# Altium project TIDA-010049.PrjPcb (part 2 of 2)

## Sheet TIDA-010049_DigitalInputChan.SchDoc
size 431 x 279 mm; Date: Not shown in title block; ApprovedBy: Not shown in title block; CheckedBy: Not shown in title block; Author: Not shown in title block; CompanyName: Not shown in title block; Engineer: Not shown in title block; Organization: Not shown in title block; Address1: Not shown in title block; Address2: Not shown in title block; Address3: Not shown in title block; Address4: Not shown in title block; DocumentNumber: 2; Revision: Use project parameter SCH_Rev; SheetNumber: 2; SheetTotal: 3; PageSetup: Record=PageOptions¦CenterHorizontal=True¦CenterVertical=True¦PrintScale=1.00¦XCorrection=1.00¦YCorrection=1.00¦PrintKind=0¦BorderSize=5000000¦LeftOffset=0¦BottomOffset=0¦Orientation=2¦PaperLength=1000¦PaperWidth=1000¦Scale=100¦PaperSource=15¦PrintQuality=600¦MediaType=1¦DitherType=10¦PaperKind=Letter¦PrintScaleMode=1
Used 8 times, as channels DI1, DI2, DI3, DI4, DI5, DI6, DI7, DI8. Parts and nets are listed once, with the designators drawn on the sheet.
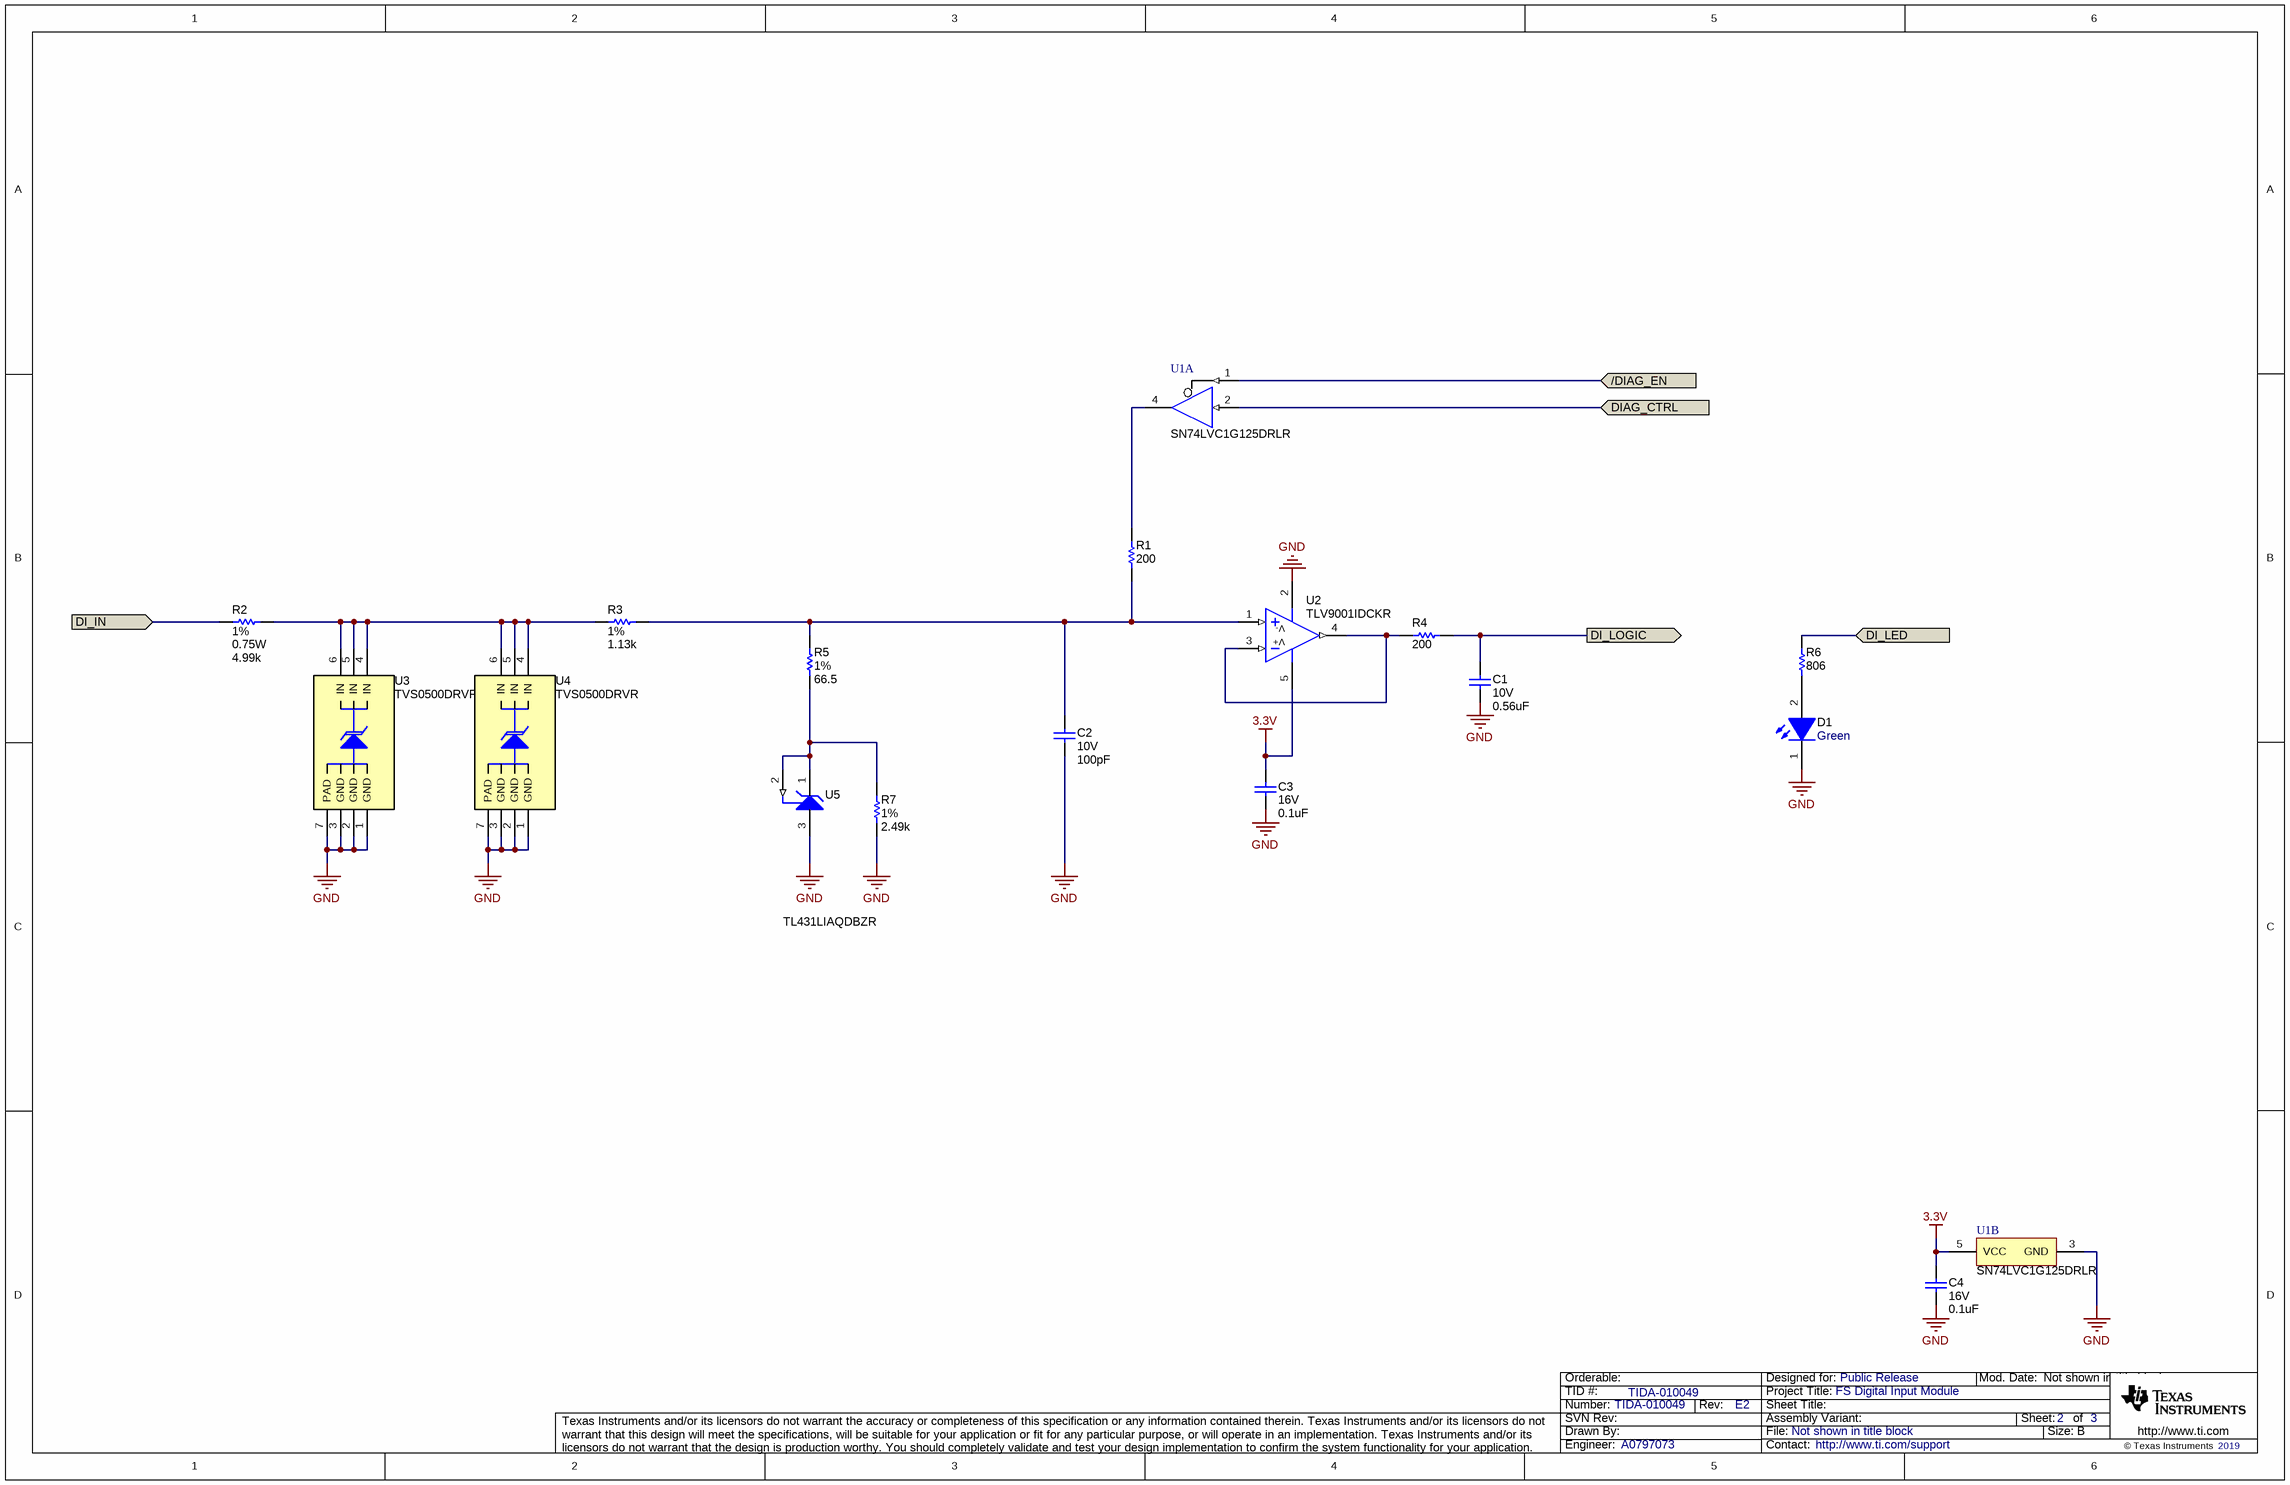
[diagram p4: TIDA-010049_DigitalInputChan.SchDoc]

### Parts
C1  VDC_V: 10V  ValueDisplayed: 0.56uF  [0603]  (hidden comment: GRM188R71A564KA61D)
C2  VDC_V: 10V  ValueDisplayed: 100pF  [0603]  (hidden comment: 0603ZC101KAT2A)
C3  VDC_V: 16V  ValueDisplayed: 0.1uF  [0603]  (hidden comment: GRM188R71C104KA01D)
C4  VDC_V: 16V  ValueDisplayed: 0.1uF  [0603]  (hidden comment: GRM188R71C104KA01D)
D1  value Green  [WL-SMCW_GREEN]  (hidden comment: 150060GS75000)
R1  ValueDisplayed: 200  [0603]  (hidden comment: CRCW0603200RJNEA)
R2  Tolerance_%: 1%  Value2: 0.75W  ValueDisplayed: 4.99k  [2010]  (hidden comment: CRCW20104K99FKEF)
R3  Tolerance_%: 1%  ValueDisplayed: 1.13k  [0603]  (hidden comment: RC0603FR-071K13L)
R4  ValueDisplayed: 200  [0603]  (hidden comment: CRCW0603200RJNEA)
R5  Tolerance_%: 1%  ValueDisplayed: 66.5  [0603]  (hidden comment: RC0603FR-0766R5L)
R6  ValueDisplayed: 806  [0603]  (hidden comment: RC0603FR-07806RL)
R7  Tolerance_%: 1%  ValueDisplayed: 2.49k  [0603]  (hidden comment: RC0603FR-072K49L)
U1  SN74LVC1G125DRLR  [DRL0005A]  (parts A,B of 2)
U2  TLV9001IDCKR  [DCK0005A_N]
U3  TVS0500DRVR  [DRV0006A]
U4  TVS0500DRVR  [DRV0006A]
U5  TL431LIAQDBZR  [DBZ0003A_N]

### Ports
/DIAG_EN (in), DI_IN (in), DI_LED (in), DI_LOGIC (out), DIAG_CTRL (in)

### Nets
3.3V: C3.1 C4.1 U1.5(VCC) U2.5(V+)
GND: C1.2 C2.2 C3.2 C4.2 D1.1(K) R7.1 U1.3(GND) U2.2(V-) U3.1(GND) U3.2(GND) U3.3(GND) U3.7(PAD) U4.1(GND) U4.2(GND) U4.3(GND) U4.7(PAD) U5.3(ANODE)
/DIAG_EN: U1.1(~{OE}) ; port /DIAG_EN
DI_IN: R2.2 ; port DI_IN
DI_LED: R6.2 ; port DI_LED
DI_LOGIC: C1.1 R4.2 ; port DI_LOGIC
DIAG_CTRL: U1.2(A) ; port DIAG_CTRL
NetC2_1: C2.1 R1.1 R3.1 R5.2 U2.1(IN+)
NetD1_2: D1.2(A) R6.1
NetR1_2: R1.2 U1.4(Y)
NetR2_1: R2.1 R3.2 U3.4(IN) U3.5(IN) U3.6(IN) U4.4(IN) U4.5(IN) U4.6(IN)
NetR4_1: R4.1 U2.3(IN-) U2.4(OUT)
NetR5_1: R5.1 R7.2 U5.1(CATHODE) U5.2(REF)

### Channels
DI1: designators end in _1; ports /DIAG_EN=/DIAG_EN1 DI_IN=DI_IN1 DI_LED=DI_LED1 DI_LOGIC=DI_LOGIC1 DIAG_CTRL=DIAG_CTRL1
DI2: designators end in _2; ports /DIAG_EN=/DIAG_EN2 DI_IN=DI_IN2 DI_LED=DI_LED2 DI_LOGIC=DI_LOGIC2 DIAG_CTRL=DIAG_CTRL2
DI3: designators end in _3; ports /DIAG_EN=/DIAG_EN3 DI_IN=DI_IN3 DI_LED=DI_LED3 DI_LOGIC=DI_LOGIC3 DIAG_CTRL=DIAG_CTRL3
DI4: designators end in _4; ports /DIAG_EN=/DIAG_EN4 DI_IN=DI_IN4 DI_LED=DI_LED4 DI_LOGIC=DI_LOGIC4 DIAG_CTRL=DIAG_CTRL4
DI5: designators end in _5; ports /DIAG_EN=/DIAG_EN5 DI_IN=DI_IN5 DI_LED=DI_LED5 DI_LOGIC=DI_LOGIC5 DIAG_CTRL=DIAG_CTRL5
DI6: designators end in _6; ports /DIAG_EN=/DIAG_EN6 DI_IN=DI_IN6 DI_LED=DI_LED6 DI_LOGIC=DI_LOGIC6 DIAG_CTRL=DIAG_CTRL6
DI7: designators end in _7; ports /DIAG_EN=/DIAG_EN7 DI_IN=DI_IN7 DI_LED=DI_LED7 DI_LOGIC=DI_LOGIC7 DIAG_CTRL=DIAG_CTRL7
DI8: designators end in _8; ports /DIAG_EN=/DIAG_EN8 DI_IN=DI_IN8 DI_LED=DI_LED8 DI_LOGIC=DI_LOGIC8 DIAG_CTRL=DIAG_CTRL8

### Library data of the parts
C1 = CMP-0007374-4: CAP, CERM, 0.56 uF, 10 V, +/- 10%, X7R, 0603; Manufacturer: MuRata; TaMin_C: -55°C; Polarized: N; SizeAreaWB_mm2: 4.68; Value1: Unknown; U/M: EA; Value: 0.56uF; TaMax_C: 125°C; SizeZ_mm: 1; SizeX_mm: 1.6; SizeY_mm: 0.8; SizeArea_mm2: 1.28; Cap_F: 560nF; AEC Category: Q200
C2 = CMP-0006812-4: CAP, CERM, 100 pF, 10 V, +/- 10%, X7R, 0603; Manufacturer: AVX; TaMin_C: -55°C; Polarized: N; SizeAreaWB_mm2: 4.68; Value1: Unknown; U/M: EA; Value: 100pF; TaMax_C: 125°C; SizeZ_mm: 1; SizeX_mm: 1.6; SizeY_mm: 0.8; SizeArea_mm2: 1.28; AEC Category: Q200
C3 C4 = CMP-0007378-5: CAP, CERM, 0.1 uF, 16 V, +/- 10%, X7R, 0603; Manufacturer: MuRata; TaMin_C: -55°C; Polarized: N; SizeAreaWB_mm2: 4.68; Value1: Unknown; U/M: EA; Value: 0.1uF; TaMax_C: 125°C; SizeZ_mm: 1; SizeX_mm: 1.6; SizeY_mm: 0.8; SizeArea_mm2: 1.28; Cap_F: 100nF; AEC Category: Q200
D1 = CMP-0002905-2: LED, Green, SMD; Manufacturer: Wurth Elektronik; Value1: W; Type: InGaN; Value2: 3.2V; Io_A: 20mA; Angle: 140; Tjmax_C: 85°C
R1 R4 = CMP-0025752-3: RES, 200, 5%, 0.1 W, 0603; Manufacturer: Vishay-Dale; Power_W: 100mW; TempCo: 200 ppm/C; Value_Code: 200R; U/M: EA; Value: 200; EIA_Code: E24; SizeX_mm: 1.6; SizeY_mm: 0.8; SizeZ_mm: 1; Value2: 0.1W; SizeArea_mm2: 1.28; VDC_V: 75V; AEC Category: Q200
R2 = CMP-0016428-1: RES, 4.99 k, 1%, 0.75 W, AEC-Q200 Grade 0, 2010; Manufacturer: Vishay-Dale; Power_W: 750mW; TempCo: 100 ppm/C; Value_Code: 4k99; U/M: EA; Value: 4.99k; EIA_Code: E96; SizeX_mm: 5; SizeY_mm: 2.5; SizeZ_mm: 1.66; SizeArea_mm2: 12.5; AEC Qualified: Y; VDC_V: 400V; AEC Grade: 0; AEC Category: Q200
R3 = CMP-0022867-5: RES, 1.13 k, 1%, 0.1 W, 0603; Manufacturer: Yageo; Power_W: 100mW; TempCo: 100 ppm/C; Value_Code: 1k13; Value: 1.13k; EIA_Code: E96; SizeX_mm: 1.6; SizeY_mm: 0.8; SizeZ_mm: 1; Value2: 0.1W; SizeArea_mm2: 1.28; AEC Qualified: N; VDC_V: 75V; AEC Category: Q200; SizeAreaWB_mm2: 4.68
R5 = CMP-0023233-5: RES, 66.5, 1%, 0.1 W, 0603; Manufacturer: Yageo; Power_W: 100mW; TempCo: 100 ppm/C; Value_Code: 66R5; Value: 66.5; EIA_Code: E96; SizeX_mm: 1.6; SizeY_mm: 0.8; SizeZ_mm: 1; Value2: 0.1W; SizeArea_mm2: 1.28; AEC Qualified: N; VDC_V: 75V; AEC Category: Q200; SizeAreaWB_mm2: 4.68
R6 = CMP-0023284-5: RES, 806, 1%, 0.1 W, 0603; Manufacturer: Yageo; Power_W: 100mW; TempCo: 100 ppm/C; Value_Code: 806R; Value: 806; EIA_Code: E96; SizeX_mm: 1.6; SizeY_mm: 0.8; SizeZ_mm: 1; Value2: 0.1W; SizeArea_mm2: 1.28; AEC Qualified: N; VDC_V: 75V; AEC Category: Q200; SizeAreaWB_mm2: 4.68
R7 = CMP-0022990-5: RES, 2.49 k, 1%, 0.1 W, 0603; Manufacturer: Yageo; Power_W: 100mW; TempCo: 100 ppm/C; Value_Code: 2k49; Value: 2.49k; EIA_Code: E96; SizeX_mm: 1.6; SizeY_mm: 0.8; SizeZ_mm: 1; Value2: 0.1W; SizeArea_mm2: 1.28; AEC Qualified: N; VDC_V: 75V; AEC Category: Q200; SizeAreaWB_mm2: 4.68
U1 = CMP-0051312-3: Single Bus Buffer Gate With 3-State Outputs, DRL0005A, LARGE T&R; Manufacturer: Texas Instruments; Output Type: CMOS; tpd @ Nom Voltage(Max)(ns): 9,5.5,4.5,4; Schmitt Trigger: No; Input Type: CMOS/TTL; Voltage(Nom)(V): 1.8,2.5,3.3,5; Technology Family: LVC; VCC(Max)(V): 5.5; F @ Nom Voltage(Max)(Mhz): 150; Sub-Family: Non-Inverting Buffer/Driver; Bits(#): 1; ICC @ Nom Voltage(Max)(mA): 0.01; Rating: Catalog; VCC(Min)(V): 1.65; Logic: True; Output Drive (IOL/IOH)(Max)(mA): 32/-32; 3-State Output: Yes; AEC Category: Q200; AEC Qualified: N; CompType: IC; SizeX_mm: 1.6; SizeZ_mm: 0.6
U2 = CMP-0081556-1: Low-Power, Rail-to-Rail In and Out, 1-MHz Operational Amplifier, DCK0005A (SOT-SC70-5); Alternate PartNumber: TLV9001IDCKT; Alternate Manufacturer: Texas Instruments; SizeAreaWB_mm2: 9.3; SizeZ_mm: 1.1; SizeX_mm: 2.1; SizeY_mm: 2; SizeArea_mm2: 4.2; CompType: IC; AEC Qualified: N; AEC Category: Q200
U3 U4 = CMP-0077837-1: 5-V Precision Surge Protection Clamp, DRV0006A (WSON-6); Alternate Manufacturer: Texas Instruments; SizeAreaWB_mm2: 9.0; SizeZ_mm: 0.8; SizeX_mm: 2.0; SizeArea_mm2: 4.0; CompType: IC; AEC Qualified: N; AEC Category: Q200
U5 = CMP-0084728-1: Programmable Shunt Regulator with Optimized Reference Current, DBZ0003A (SOT-23-3); Manufacturer: Texas Instruments; AEC Qualified: N; SizeZ_mm: 1.12; CompType: IC; SizeY_mm: 3; AEC Category: Q200; SizeX_mm: 2.5; SizeAreaWB_mm2: 14; SizeArea_mm2: 7.5

## Sheet TIDA-010049_LED.SchDoc
size 431 x 279 mm; Date: Not shown in title block; ApprovedBy: Not shown in title block; CheckedBy: Not shown in title block; Author: Not shown in title block; CompanyName: Not shown in title block; Engineer: Not shown in title block; Organization: Not shown in title block; Address1: Not shown in title block; Address2: Not shown in title block; Address3: Not shown in title block; Address4: Not shown in title block; DocumentNumber: 2; Revision: Use project parameter SCH_Rev; SheetNumber: 2; SheetTotal: 3; PageSetup: Record=PageOptions¦CenterHorizontal=True¦CenterVertical=True¦PrintScale=1.00¦XCorrection=1.00¦YCorrection=1.00¦PrintKind=0¦BorderSize=5000000¦LeftOffset=0¦BottomOffset=0¦Orientation=2¦PaperLength=1000¦PaperWidth=1000¦Scale=100¦PaperSource=15¦PrintQuality=600¦MediaType=1¦DitherType=10¦PaperKind=Letter¦PrintScaleMode=1
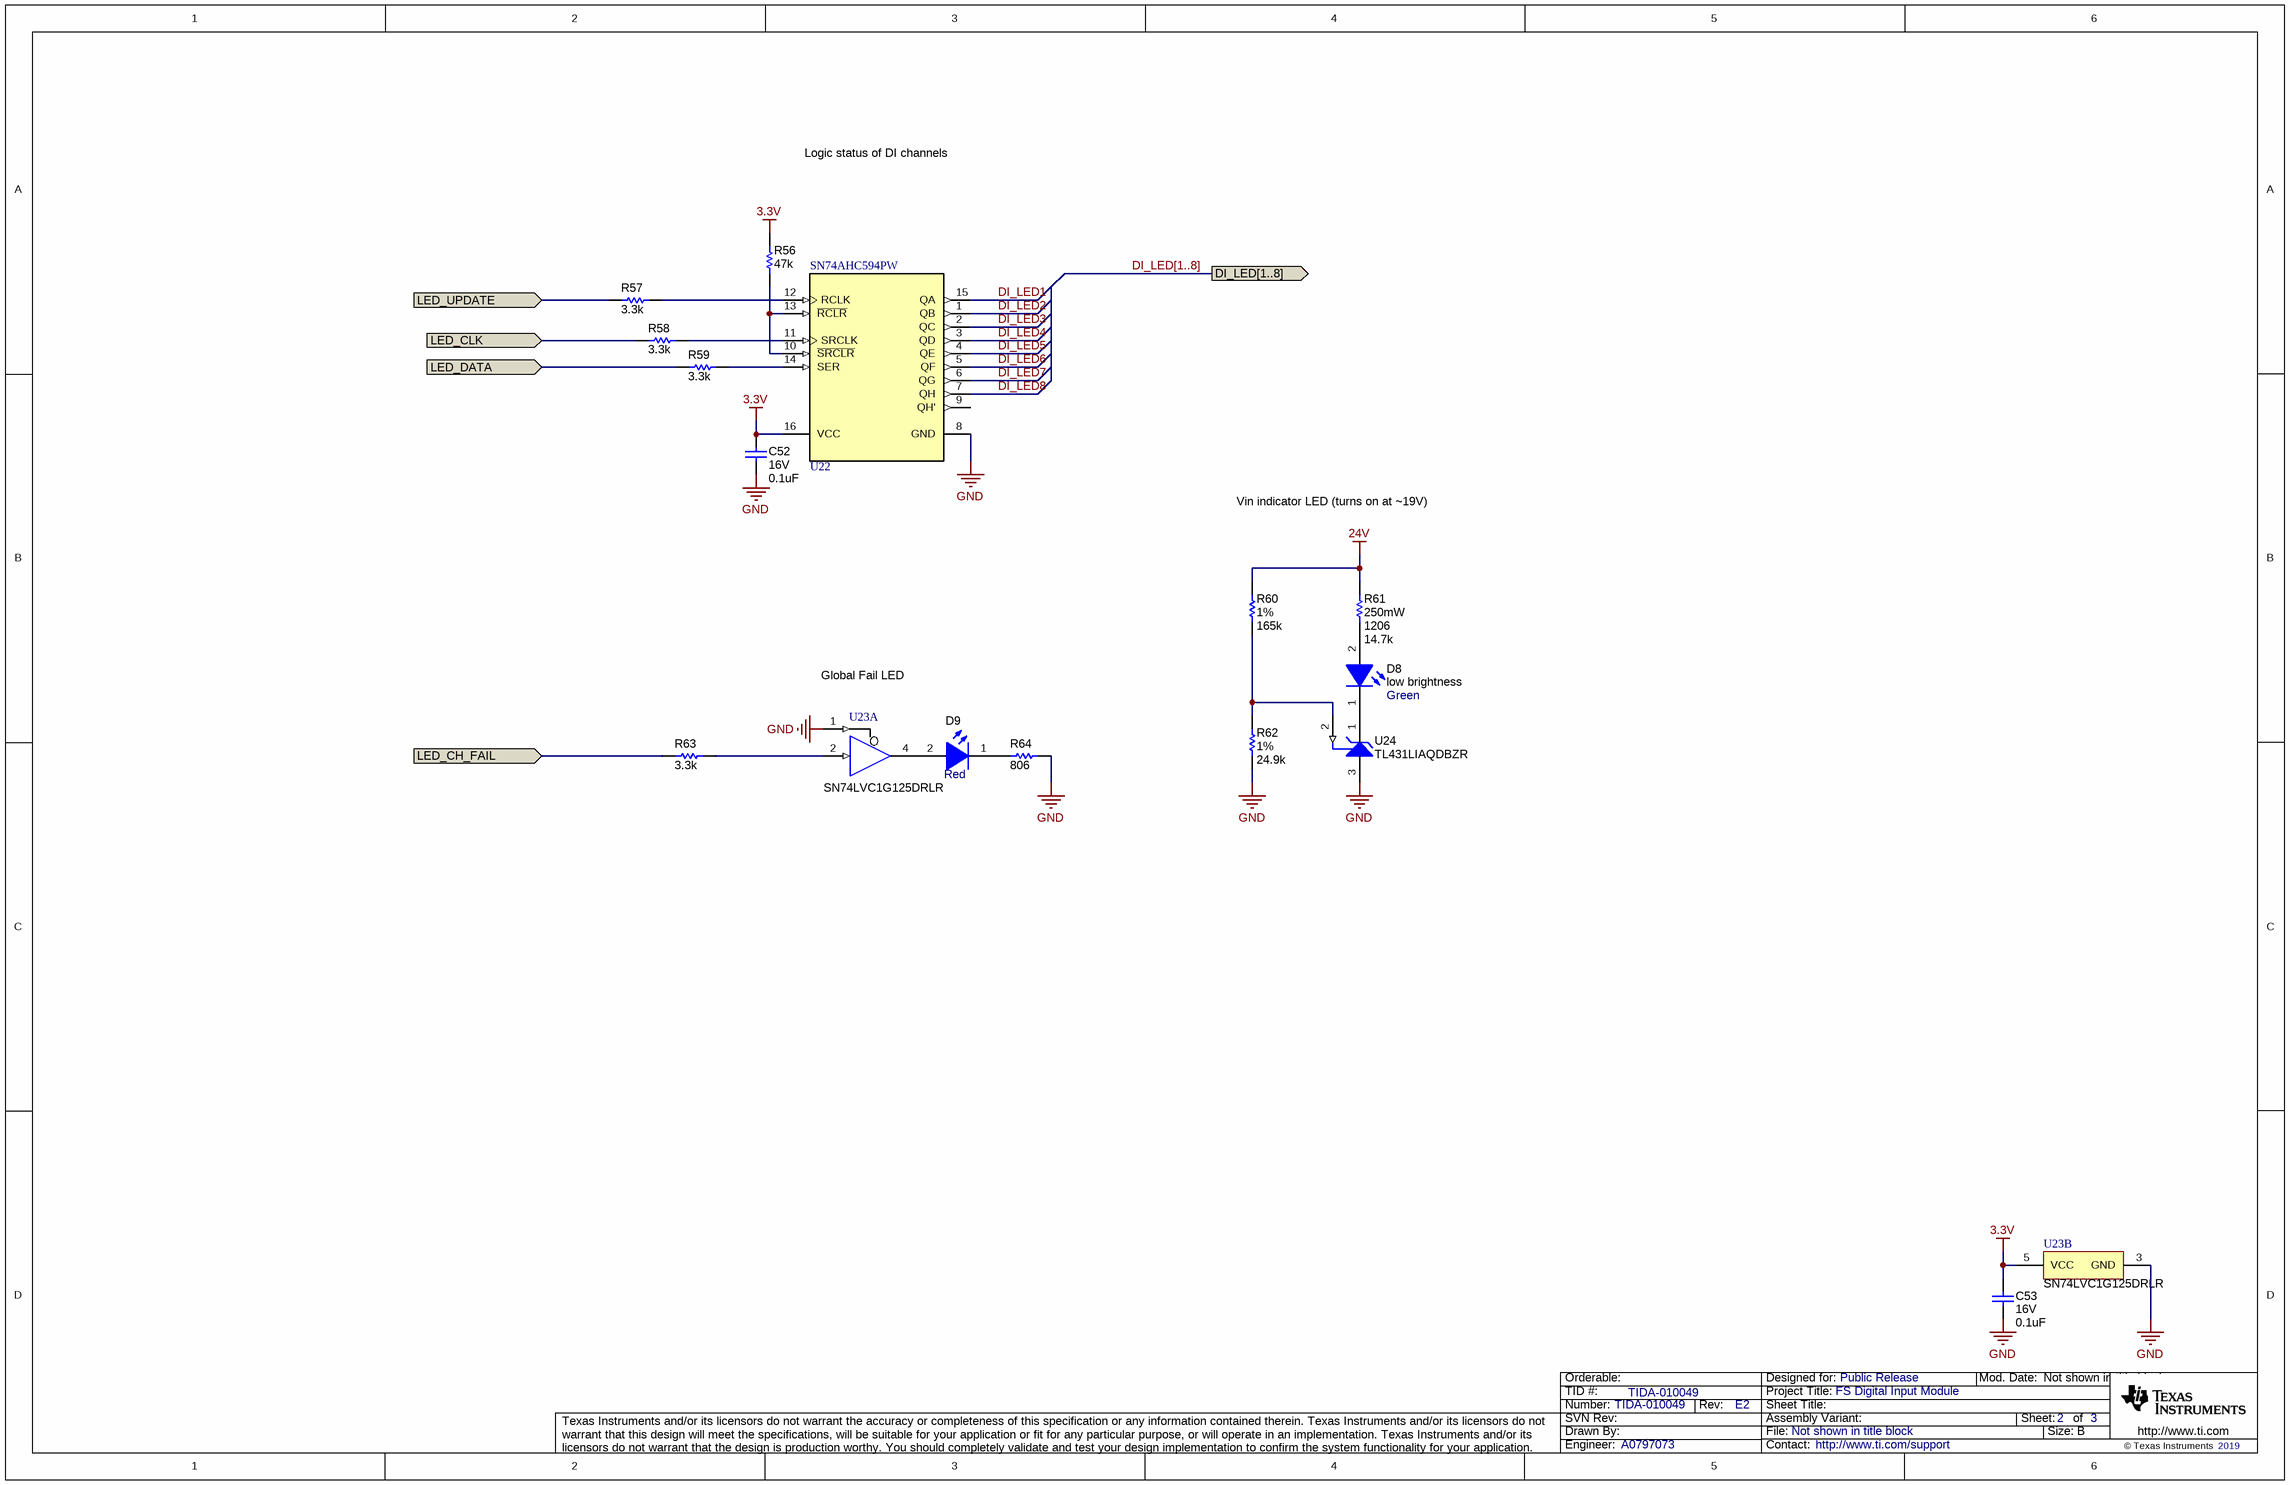
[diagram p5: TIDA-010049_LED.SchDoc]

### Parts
C52  VDC_V: 16V  ValueDisplayed: 0.1uF  [0603]  (hidden comment: GRM188R71C104KA01D)
C53  VDC_V: 16V  ValueDisplayed: 0.1uF  [0603]  (hidden comment: GRM188R71C104KA01D)
D8  low brightness  value Green  [WL-SMCW_GREEN]
D9  value Red  [WL-SMCW_RED]  (hidden comment: 150060RS75000)
R56  ValueDisplayed: 47k  [0603]  (hidden comment: RC0603JR-0747KL)
R57  ValueDisplayed: 3.3k  [0603]  (hidden comment: RC0603JR-073K3L)
R58  ValueDisplayed: 3.3k  [0603]  (hidden comment: RC0603JR-073K3L)
R59  ValueDisplayed: 3.3k  [0603]  (hidden comment: RC0603JR-073K3L)
R60  Tolerance_%: 1%  ValueDisplayed: 165k  [0603]  (hidden comment: RC0603FR-07165KL)
R61  Power_W: 250mW  ValueDisplayed: 14.7k  [1206]  (hidden comment: RC1206FR-0714K7L)
R62  Tolerance_%: 1%  ValueDisplayed: 24.9k  [0603]  (hidden comment: RC0603FR-0724K9L)
R63  ValueDisplayed: 3.3k  [0603]  (hidden comment: RC0603JR-073K3L)
R64  ValueDisplayed: 806  [0603]  (hidden comment: RC0603FR-07806RL)
U22  SN74AHC594PW  [PW0016A_N]
U23  SN74LVC1G125DRLR  [DRL0005A]  (parts A,B of 2)
U24  TL431LIAQDBZR  [DBZ0003A_N]

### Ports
DI_LED[1..8] (out), LED_CH_FAIL (in), LED_CLK (in), LED_DATA (in), LED_UPDATE (in)

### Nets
3.3V: C52.1 C53.1 R56.1 U22.16(VCC) U23.5(VCC)
24V: R60.1 R61.1
GND: C52.2 C53.2 R62.2 R64.1 U22.8(GND) U23.1(~{OE}) U23.3(GND) U24.3(ANODE)
DI_LED1: U22.15(QA)
DI_LED2: U22.1(QB)
DI_LED3: U22.2(QC)
DI_LED4: U22.3(QD)
DI_LED5: U22.4(QE)
DI_LED6: U22.5(QF)
DI_LED7: U22.6(QG)
DI_LED8: U22.7(QH)
LED_CH_FAIL: R63.1 ; port LED_CH_FAIL
LED_CLK: R58.1 ; port LED_CLK
LED_DATA: R59.1 ; port LED_DATA
LED_UPDATE: R57.1 ; port LED_UPDATE
NetD8_1: D8.1(K) U24.1(CATHODE)
NetD8_2: D8.2(A) R61.2
NetD9_1: D9.1(K) R64.2
NetD9_2: D9.2(A) U23.4(Y)
NetR56_2: R56.2 U22.10(~{SRCLR}) U22.13(~{RCLR})
NetR57_2: R57.2 U22.12(RCLK)
NetR58_2: R58.2 U22.11(SRCLK)
NetR59_2: R59.2 U22.14(SER)
NetR60_2: R60.2 R62.1 U24.2(REF)
NetR63_2: R63.2 U23.2(A)

Not connected (* = marked no-connect by the designer): U22 9(QH')

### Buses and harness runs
bus DI_LED[1..8] = port DI_LED[1..8]

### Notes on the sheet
- Logic status of DI channels
- Vin indicator LED (turns on at
  9V)
- (near U23) Global Fail LED

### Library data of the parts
C52 C53 = CMP-0007378-5: as C3 on sheet TIDA-010049_DigitalInputChan
D8 = CMP-0002894-2: LED, Green, SMD; Manufacturer: Wurth Elektronik; PartNumber: 150060VS75000; Type: AlInGaP; Value2: 2V; Io_A: 20mA; Value1: W
D9 = CMP-0002947-1: LED, Red, SMD; Manufacturer: Wurth Elektronik; Io_A: 30mA; Power_TotalModule: 72mW; Vr_V: 5V; Tjmax_C: 85°C; Value1: 0.072W; U/M: EA; Angle: 140; Vf_V: 2V; Type: AlInGaP
R56 = CMP-0025925-5: RES, 47 k, 5%, 0.1 W, 0603; Manufacturer: Yageo; Power_W: 100mW; TempCo: 100 ppm/C; Value_Code: 47k0; Value: 47k; EIA_Code: E24; SizeX_mm: 1.6; SizeY_mm: 0.8; SizeZ_mm: 1; Value2: 0.1W; SizeArea_mm2: 1.28; AEC Qualified: N; VDC_V: 75V; AEC Category: Q200; SizeAreaWB_mm2: 4.68
R57-R59 R63 = CMP-0025918-5: RES, 3.3 k, 5%, 0.1 W, 0603; Manufacturer: Yageo; Power_W: 100mW; TempCo: 100 ppm/C; Value_Code: 3k30; Value: 3.3k; EIA_Code: E24; SizeX_mm: 1.6; SizeY_mm: 0.8; SizeZ_mm: 1; Value2: 0.1W; SizeArea_mm2: 1.28; AEC Qualified: N; VDC_V: 75V; AEC Category: Q200; SizeAreaWB_mm2: 4.68
R60 = CMP-0022824-4: RES, 165 k, 1%, 0.1 W, 0603; Manufacturer: Yageo; Power_W: 100mW; TempCo: 100 ppm/C; Value: 165k; EIA_Code: E96; SizeX_mm: 1.6; SizeY_mm: 0.8; SizeZ_mm: 1; Value2: 0.1W; SizeArea_mm2: 1.28; AEC Qualified: N; VDC_V: 75V; AEC Category: Q200; SizeAreaWB_mm2: 4.68
R61 = CMP-0017903-2: RES, 14.7 k, 1%, 0.25 W, 1206; Manufacturer: Yageo America; TempCo: 100 ppm/C; Value_Code: 14k7; U/M: EA; Value: 14.7k; EIA_Code: E96; SizeX_mm: 3.2; SizeY_mm: 1.6; SizeZ_mm: 1.35; Value2: 0.25W; SizeArea_mm2: 5.12; VDC_V: 200V; AEC Category: Q200
R62 = CMP-0022944-5: RES, 24.9 k, 1%, 0.1 W, 0603; Manufacturer: Yageo; Power_W: 100mW; TempCo: 100 ppm/C; Value_Code: 24k9; Value: 24.9k; EIA_Code: E96; SizeX_mm: 1.6; SizeY_mm: 0.8; SizeZ_mm: 1; Value2: 0.1W; SizeArea_mm2: 1.28; AEC Qualified: N; VDC_V: 75V; AEC Category: Q200; SizeAreaWB_mm2: 4.68
R64 = CMP-0023284-5: as R6 on sheet TIDA-010049_DigitalInputChan
U22 = CMP-0053860-1: 8-Bit Shift Registers With Output Registers, PW0016A, TUBE; Manufacturer: Texas Instruments; F @ Nom Voltage(Max)(Mhz): 110; Output Type: CMOS; Output Drive (IOL/IOH)(Max)(mA): 50/-50; Rating: Catalog; Bits: 8; Voltage(Nom)(V): 3.3, 5; VCC(Max)(V): 5.5; ICC @ Nom Voltage(Max)(mA): 0.04; tpd @ Nom Voltage(Max)(ns): 13.9, 10.1; Technology Family: AHC; 3-State Output: No; VCC(Min)(V): 2
U23 = CMP-0051312-3: as U1 on sheet TIDA-010049_DigitalInputChan
U24 = CMP-0084728-1: as U5 on sheet TIDA-010049_DigitalInputChan

## Sheet TIDA-010049_Hardware.SchDoc
size 431 x 279 mm; Date: Not shown in title block; ApprovedBy: Not shown in title block; CheckedBy: Not shown in title block; Author: Not shown in title block; CompanyName: Not shown in title block; Engineer: Not shown in title block; Organization: Not shown in title block; Address1: Not shown in title block; Address2: Not shown in title block; Address3: Not shown in title block; Address4: Not shown in title block; DocumentNumber: 2; Revision: Use project parameter SCH_Rev; SheetNumber: 2; SheetTotal: 3; PageSetup: Record=PageOptions¦CenterHorizontal=True¦CenterVertical=True¦PrintScale=1.00¦XCorrection=1.00¦YCorrection=1.00¦PrintKind=0¦BorderSize=5000000¦LeftOffset=0¦BottomOffset=0¦Orientation=2¦PaperLength=1000¦PaperWidth=1000¦Scale=100¦PaperSource=15¦PrintQuality=600¦MediaType=1¦DitherType=10¦PaperKind=Letter¦PrintScaleMode=1
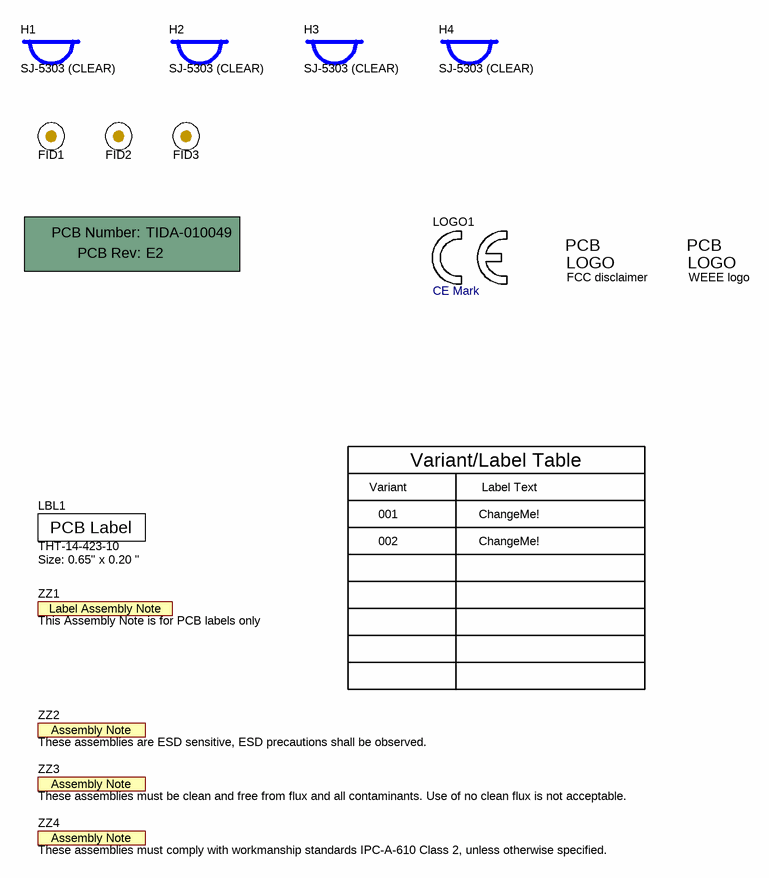
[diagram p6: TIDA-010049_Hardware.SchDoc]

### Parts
!PCB1  Printed Circuit Board  (value not drawn)  (mechanical)
FID1  Fiducial  [Fiducial10-20]  (value not drawn)
FID2  Fiducial  [Fiducial10-20]  (value not drawn)
FID3  Fiducial  [Fiducial10-20]  (value not drawn)
H1  SJ-5303 (CLEAR)  [Bumpon_SJ5003Transparent]
H2  SJ-5303 (CLEAR)  [Bumpon_SJ5003Transparent]
H3  SJ-5303 (CLEAR)  [Bumpon_SJ5003Transparent]
H4  SJ-5303 (CLEAR)  [Bumpon_SJ5003Transparent]
LBL1  THT-14-423-10  Note: Size: 0.65" x 0.20 "  [Label_650x200]
LOGO1  CE Mark  [CE_Mark_5mm]  (no BOM)
Logo3  FCC disclaimer  [FCC_disclaimer]  (no BOM)
Logo4  WEEE logo  [WEEE_Minimum]  (no BOM)
ZZ1  This Assembly Note is for PCB labels only  [AssemblyNoteLabel]  (no BOM)
ZZ2  These assemblies are ESD sensitive, ESD precautions shall be observed.  [AssemblyNote]  (no BOM)
ZZ3  These assemblies must be clean and free from flux and all contaminants. Use of no clean flux is not acceptable.  [AssemblyNote]  (no BOM)
ZZ4  These assemblies must comply with workmanship standards IPC-A-610 Class 2, unless otherwise specified.  [AssemblyNote]  (no BOM)

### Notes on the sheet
- Variant
- Variant/Label Table
- Label Text
- 001
- 002
- ChangeMe!

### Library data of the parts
!PCB1 = CMP-0003618-2: Manufacturer: Any; PartNumber: TIDA-010049
FID1-FID3 = CMP-0077181-1: Fiducial mark.  There is nothing to buy or mount.
H1-H4 = CMP-0003620-1: Bumpon, Hemisphere, 0.44 X 0.20, Clear; Manufacturer: 3M
LBL1 = CMP-0003625-1: Thermal Transfer Printable Labels, 0.650" W x 0.200" H - 10,000 per roll; Manufacturer: Brady; CompType: Label
LOGO1 = CMP-0074844-1: SymbolCreator: a0412235
Logo3 = CMP-0074847-1: FCC_disclaimer; Library Reference: Logo
Logo4 = CMP-0074769-1
ZZ1 = CMP-0003616-3
ZZ2 = CMP-0077236-1
ZZ3 = CMP-0077237-1
ZZ4 = CMP-0077238-1

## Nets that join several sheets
1.25V: TIDA-010049_Hercules (18 pins), TIDA-010049_Power (C41.1 L3.2 R40.1 U16.6)
3.3V: TIDA-010049_Hercules (33 pins), TIDA-010049_Power (23 pins), DI1 (C3_1.1 C4_1.1 U1_1.5 U2_1.5), DI2 (C3_2.1 C4_2.1 U1_2.5 U2_2.5), DI3 (C3_3.1 C4_3.1 U1_3.5 U2_3.5), DI4 (C3_4.1 C4_4.1 U1_4.5 U2_4.5), DI5 (C3_5.1 C4_5.1 U1_5.5 U2_5.5), DI6 (C3_6.1 C4_6.1 U1_6.5 U2_6.5), DI7 (C3_7.1 C4_7.1 U1_7.5 U2_7.5), DI8 (C3_8.1 C4_8.1 U1_8.5 U2_8.5), TIDA-010049_LED (5 pins)
24V: TIDA-010049_Power (13 pins), TIDA-010049_LED (R60.1 R61.1)
DGND: TIDA-010049_Top (J3.1), TIDA-010049_Hercules (C28.2 R28.2 U13.2 U13.8)
DVDD: TIDA-010049_Top (J3.6), TIDA-010049_Hercules (C28.1 U13.1)
GND: TIDA-010049_Hercules (68 pins), TIDA-010049_Power (36 pins), DI1 (17 pins), DI2 (17 pins), DI3 (17 pins), DI4 (17 pins), DI5 (17 pins), DI6 (17 pins), DI7 (17 pins), DI8 (17 pins), TIDA-010049_LED (8 pins)
/DIAG_EN1: TIDA-010049_Hercules (U7.67), DI1 (U1_1.1)
/DIAG_EN2: TIDA-010049_Hercules (U7.73), DI2 (U1_2.1)
/DIAG_EN3: TIDA-010049_Hercules (U7.93), DI3 (U1_3.1)
/DIAG_EN4: TIDA-010049_Hercules (U7.27), DI4 (U1_4.1)
/DIAG_EN5: TIDA-010049_Hercules (U7.39), DI5 (U1_5.1)
/DIAG_EN6: TIDA-010049_Hercules (U7.68), DI6 (U1_6.1)
/DIAG_EN7: TIDA-010049_Hercules (U7.65), DI7 (U1_7.1)
/DIAG_EN8: TIDA-010049_Hercules (U7.66), DI8 (U1_8.1)
/FLT_1.25V_OV: TIDA-010049_Hercules (U6.6), TIDA-010049_Power (R39.1 U19.1)
/FLT_1.25V_UV: TIDA-010049_Hercules (D4.1 U6.1), TIDA-010049_Power (R38.1 U19.6)
/FLT_3.3V_OV: TIDA-010049_Hercules (U7.2), TIDA-010049_Power (R42.2 U17.1)
/FLT_4.3V: TIDA-010049_Hercules (U7.9), TIDA-010049_Power (R37.2 U18.1 U18.6)
/FLT_SENSSUP: TIDA-010049_Hercules (U7.10), TIDA-010049_Power (R49.1 TP20.1 U21.9)
/FLT_TEMP: TIDA-010049_Hercules (U7.5), TIDA-010049_Power (R50.2 U20.3)
DI_IN1: TIDA-010049_Top (J5.1), DI1 (R2_1.2)
DI_IN2: TIDA-010049_Top (J5.3), DI2 (R2_2.2)
DI_IN3: TIDA-010049_Top (J5.5), DI3 (R2_3.2)
DI_IN4: TIDA-010049_Top (J5.7), DI4 (R2_4.2)
DI_IN5: TIDA-010049_Top (J6.1), DI5 (R2_5.2)
DI_IN6: TIDA-010049_Top (J6.3), DI6 (R2_6.2)
DI_IN7: TIDA-010049_Top (J6.5), DI7 (R2_7.2)
DI_IN8: TIDA-010049_Top (J6.7), DI8 (R2_8.2)
DI_LED1: DI1 (R6_1.2), TIDA-010049_LED (U22.15)
DI_LED2: DI2 (R6_2.2), TIDA-010049_LED (U22.1)
DI_LED3: DI3 (R6_3.2), TIDA-010049_LED (U22.2)
DI_LED4: DI4 (R6_4.2), TIDA-010049_LED (U22.3)
DI_LED5: DI5 (R6_5.2), TIDA-010049_LED (U22.4)
DI_LED6: DI6 (R6_6.2), TIDA-010049_LED (U22.5)
DI_LED7: DI7 (R6_7.2), TIDA-010049_LED (U22.6)
DI_LED8: DI8 (R6_8.2), TIDA-010049_LED (U22.7)
DI_LOGIC1: TIDA-010049_Hercules (U7.41), DI1 (C1_1.1 R4_1.2)
DI_LOGIC2: TIDA-010049_Hercules (U7.43), DI2 (C1_2.1 R4_2.2)
DI_LOGIC3: TIDA-010049_Hercules (U7.45), DI3 (C1_3.1 R4_3.2)
DI_LOGIC4: TIDA-010049_Hercules (U7.48), DI4 (C1_4.1 R4_4.2)
DI_LOGIC5: TIDA-010049_Hercules (U7.57), DI5 (C1_5.1 R4_5.2)
DI_LOGIC6: TIDA-010049_Hercules (U7.53), DI6 (C1_6.1 R4_6.2)
DI_LOGIC7: TIDA-010049_Hercules (U7.51), DI7 (C1_7.1 R4_7.2)
DI_LOGIC8: TIDA-010049_Hercules (U7.50), DI8 (C1_8.1 R4_8.2)
DIAG_CTRL1: TIDA-010049_Hercules (U7.19), DI1 (U1_1.2)
DIAG_CTRL2: TIDA-010049_Hercules (U7.22), DI2 (U1_2.2)
DIAG_CTRL3: TIDA-010049_Hercules (U7.25), DI3 (U1_3.2)
DIAG_CTRL4: TIDA-010049_Hercules (U7.26), DI4 (U1_4.2)
DIAG_CTRL5: TIDA-010049_Hercules (U7.83), DI5 (U1_5.2)
DIAG_CTRL6: TIDA-010049_Hercules (U7.89), DI6 (U1_6.2)
DIAG_CTRL7: TIDA-010049_Hercules (U7.90), DI7 (U1_7.2)
DIAG_CTRL8: TIDA-010049_Hercules (U7.97), DI8 (U1_8.2)
LED_CH_FAIL: TIDA-010049_Hercules (U7.64), TIDA-010049_LED (R63.1)
LED_CLK: TIDA-010049_Hercules (U7.71), TIDA-010049_LED (R58.1)
LED_DATA: TIDA-010049_Hercules (U7.70), TIDA-010049_LED (R59.1)
LED_UPDATE: TIDA-010049_Hercules (U7.23), TIDA-010049_LED (R57.1)
MASTER_SPI_CLK: TIDA-010049_Top (J3.4), TIDA-010049_Hercules (U13.4)
MASTER_SPI_CS: TIDA-010049_Top (J3.5), TIDA-010049_Hercules (U13.3)
MASTER_SPI_MISO: TIDA-010049_Top (J3.2), TIDA-010049_Hercules (R28.1 U13.6)
MASTER_SPI_MOSI: TIDA-010049_Top (J3.3), TIDA-010049_Hercules (U13.5)
SENSSUP: TIDA-010049_Top (8 pins), TIDA-010049_Power (C50.1 D7.2 U21.10)
SENSSUP_CTRL: TIDA-010049_Hercules (U7.12), TIDA-010049_Power (R51.2 TP19.1 U21.4)
V_GND: TIDA-010049_Top (J4.2), TIDA-010049_Power (D5.1 D7.1 Q1.3)

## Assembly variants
Standard: all parts fitted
